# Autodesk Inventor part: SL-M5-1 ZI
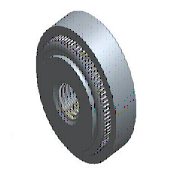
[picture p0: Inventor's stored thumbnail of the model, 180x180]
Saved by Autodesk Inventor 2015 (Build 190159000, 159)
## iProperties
Created: 2014-02
Part Number: SL-M5-1 ZI
Material: Steel, Carbon
Catalog Web Link: www.pemnet.com
Description: PEM Self-Clinching Nuts SL - Metric
Vendor: PennEngineering®
Document SubType Name: Modeling
Standard: PEM
Designer: rsheridan
Manufacturer: PennEngineering®
Language: en-US
Size Designation: SL-M5-1 ZI
Categories: <MemberInstance><Categories><Category DisplayName="Sheet Metal" InternalName="21944ee9-ad4d-44c9-9b1e-873eb7935d2a" Mnemonic="PEM"><Category DisplayName="Nuts"
Density: 7.85 g/cm^3
Appearance: Semi-Polished
IsCustomPart: 1
Title: Nut
Author: rsheridan
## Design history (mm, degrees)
sketch "Sketch1"
  geometry: L1 (0, 0.3)-(0, 2.98); L2 (3.77, 0)-(4.35, 0); L3 (4.35, 0)-(4.35, 2); L4 (4.35, 2)-(3.87, 2); L5 (3.87, 2)-(3.87, 2.49); L6 (3.87, 2.49)-(3.51, 2.49); L7 (3.19, 2.735)-(3.19, 2.98); L8 (3.19, 2.98)-(0, 2.98); L9 (3.19, 2.735)-(2.991, 2.39); L10 (2.991, 2.39)-(3.453, 2.39); L11 (3.453, 2.39)-(3.51, 2.49); L12 (3.77, 0)-(3.77, 0.3); L13 (3.77, 0.3)-(0, 0.3); 1 further point
  constraints: 26 end point, 5 parallel, 5 perpendicular, 2 point on line, 1 vertical
  dimensions: "d0" = 2 distance between parallel lines of L4 L2 (= T_); "d1" = 0.98 distance between parallel lines of L8 L4 (= A_); "d2" = 6.38 diameter of L7 L1 (= C_); "d3" = 8.7 diameter of L3 L1 (= E_); "d17" = 0.49 distance between parallel lines of L6 L4 (= 0.5 x A_); "d18" = 7.74 diameter of L5 L1 (derived); "d19" = 0.245 distance from line of L7.start L8 (= 0.25 x A_); "d20" = 30 deg angle of L9 L7; "d21" = 0.1 distance between parallel lines of L6 L10 (derived); "d23" = 0.4 distance between parallel lines of L11 L9 (derived); "d49" = 0.3 distance between parallel lines of L13 L2 (derived); "d50" = 7.54 diameter of L12 L1 (derived)
revolve "Revolution1" sketch "Sketch1" stored, may be unused: angle "d4" = 90 deg
hole "Hole1" diameter "d7" = 4.134; stored, may be unused: countersink angle "d11" = 90 deg, drill point angle "d13" = 118 deg; dims "d5" = 10, "d6" = 10, "d8" = 6, "d9" = 4, "d10" = 2, "d12" = 8
chamfer "Chamfer1" distance "d14" = 0.3 (= C1); stored, may be unused: second distance "d15" = 2, angle "d16" = 45 deg
body "Solid1"
revolve "Revolution2" stored, may be unused: angle "d44" = 90 deg
pattern_circular "Circular Pattern1" dims angle "d46" = 360 deg
sketch "Sketch2"
  geometry: L1 (2.067, 0.6)-(2.067, 2.68) reference; L2 (2.067, 0.646)-(2.667, 0.3); L3 (2.667, 0.3)-(2.067, 0.3); L4 (2.141, 0.257)-(2.497, 0.052); L5 (-3.77, 0.3)-(3.77, 0.3) reference; L6 (2.067, 0.646)-(2.067, 0.3); 1 further point
  constraints: 8 end point, 1 collinear, 1 parallel, 1 perpendicular, 1 point on line
  dimensions: "d52" = 0.6 distance of L2.end L3.end (derived); "d53" = 30 deg angle of L2 L3; "d54" = 0.3 distance between parallel lines of L2 L4 (derived)
other parameters: "A_" = 0.98 [user parameter; used in 3 equation terms], "C_" = 6.38 [user parameter; used in 1 equation term], "E_" = 8.7 [user parameter; used in 1 equation term], "T_" = 2 [user parameter; used in 1 equation term], "K_" = 0.2 [user parameter], "C1" = 0.3 [user parameter; used in 1 equation term], "Min_Dist" = 7.1 [user parameter], "H_Size" = 6.4 [user parameter], "Min_Thick" = 1 [user parameter], "NND" = 5 [user parameter], "d55" = 0, "d56" = 0, "d57" = 0, "d58" = 0, "Height" = 2.98 [user parameter]
